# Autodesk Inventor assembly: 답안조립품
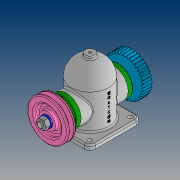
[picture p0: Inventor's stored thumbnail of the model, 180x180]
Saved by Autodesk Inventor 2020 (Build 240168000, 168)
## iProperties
Created: 2021-08
Part Number: 답안조립품
Document SubType Name: Assembly
Designer: PC312-
Author: PC312-
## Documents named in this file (14)
- C:\Users\PC312-\Desktop\710809V1008\답안조립품.iam
- C:\Users\PC312-\Desktop\710809V1008\본체.ipt
- C:\Users\PC312-\Desktop\710809V1008\커버.ipt
- C:\Users\PC312-\Desktop\710809V1008\베어링 6203.ipt
- C:\Users\PC312-\Desktop\710809V1008\축.ipt
- C:\Users\PC312-\Desktop\710809V1008\키 5x5x12.ipt
- C:\Users\PC312-\Desktop\710809V1008\V-벨트풀리.ipt
- V-벨트풀리.ipt
- C:\Users\PC312-\Desktop\710809V1008\부시.ipt
- C:\Users\PC312-\Desktop\710809V1008\스퍼기어.ipt
- C:\Users\PC312-\Desktop\710809V1008\너트 M12x1.25.ipt
- C:\Users\PC312-\Desktop\710809V1008\와셔 12x24.ipt
- C:\Users\PC312-\Desktop\710809V1008\오일 실 26 38 8.ipt
- C:\Users\PC312-\Desktop\710809V1008\볼트 M4.ipt
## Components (1 placed, 1 different names)
1. V-벨트풀리:1
